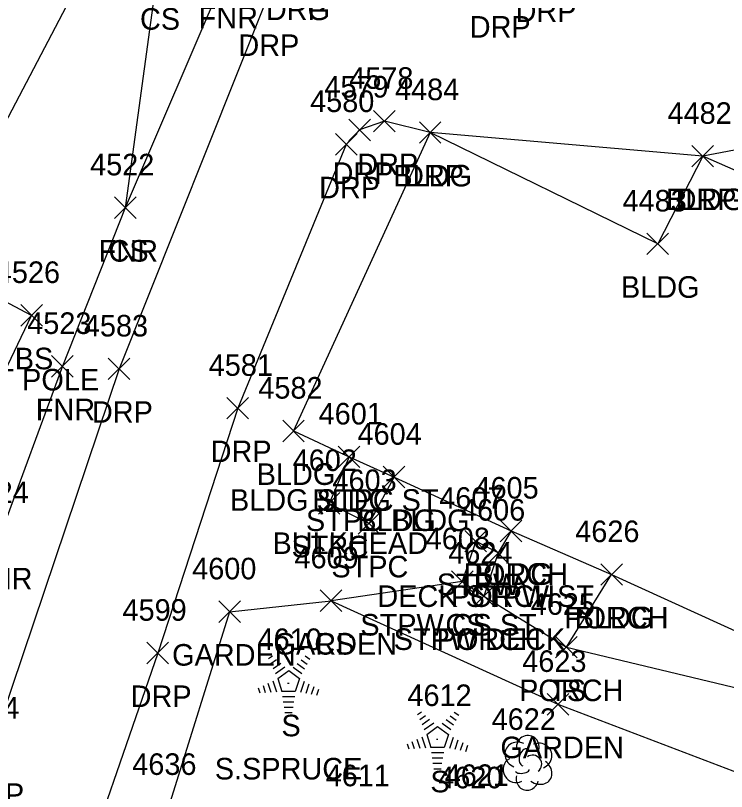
# Model space of a CAD drawing. Extents: x 49137 to 50946, y 9590 to 10709.
# Drawn here: x 50138.1 to 50204, y 10251.3 to 10323.2 of the extents above; entities that cross this region are included whole.
import ezdxf

# ---------------------------------------------------------------- set-up
doc = ezdxf.new("R2010")
doc.units = 0
for name, color, linetype in [('DCP', 7, 'Continuous'), ('L_A', 7, 'Continuous'), ('L_C', 7, 'Continuous'), ('L_I', 7, 'Continuous'), ('L_TIC', 7, 'Continuous'), ('LAPB', 7, 'Continuous'), ('LBC', 7, 'Continuous'), ('LBF', 7, 'Continuous'), ('LELB', 7, 'Continuous'), ('LFNC', 7, 'Continuous'), ('LSH', 7, 'Continuous'), ('LTC', 7, 'Continuous'), ('R_A', 7, 'Continuous'), ('R_I', 7, 'Continuous'), ('R_TIC', 7, 'Continuous'), ('RDP', 7, 'Continuous')]:
    doc.layers.add(name, color=color, linetype=linetype)

msp = doc.modelspace()

# ---------------------------------------------------------------- linework, layer by layer
at = {"layer": 'DCP'}
msp.add_lwpolyline([(49941.688, 9827.483), (50059.335, 9808.365), (50181.403, 9733.094), (50281.739, 9743.292), (50422.723, 9892.522), (50122.338, 10663.607), (50179.929, 10552.611), (50179.639, 10394.452), (50122.343, 10285.066), (50121.564, 10284.355)], dxfattribs=at)
at = {"layer": 'L_TIC'}
for points in [[(50175.537, 10311.397), (50177.537, 10313.397)], [(50177.537, 10311.397), (50175.537, 10313.397)], [(50200.782, 10309.202), (50202.782, 10311.202)], [(50202.782, 10309.202), (50200.782, 10311.202)], [(50147.29, 10304.426), (50149.29, 10306.426)], [(50149.29, 10304.426), (50147.29, 10306.426)], [(50147.29, 10304.426), (50149.29, 10306.426)], [(50149.29, 10304.426), (50147.29, 10306.426)], [(50196.617, 10301.077), (50198.617, 10303.077)], [(50198.617, 10301.077), (50196.617, 10303.077)], [(50138.611, 10294.447), (50140.611, 10296.447)], [(50140.611, 10294.447), (50138.611, 10296.447)], [(50141.462, 10289.723), (50143.462, 10291.723)], [(50143.462, 10289.723), (50141.462, 10291.723)], [(50162.875, 10283.729), (50164.875, 10285.729)], [(50164.875, 10283.729), (50162.875, 10285.729)], [(50168.018, 10281.332), (50170.018, 10283.332)], [(50170.018, 10281.332), (50168.018, 10283.332)], [(50168.018, 10281.332), (50170.018, 10283.332)], [(50170.018, 10281.332), (50168.018, 10283.332)], [(50172.191, 10279.454), (50174.191, 10281.454)], [(50174.191, 10279.454), (50172.191, 10281.454)], [(50172.191, 10279.454), (50174.191, 10281.454)], [(50174.191, 10279.454), (50172.191, 10281.454)], [(50166.179, 10277.016), (50168.179, 10279.016)], [(50168.179, 10277.016), (50166.179, 10279.016)], [(50169.868, 10275.156), (50171.868, 10277.156)], [(50171.868, 10275.156), (50169.868, 10277.156)], [(50183.024, 10274.463), (50185.024, 10276.463)], [(50185.024, 10274.463), (50183.024, 10276.463)], [(50183.024, 10274.463), (50185.024, 10276.463)], [(50185.024, 10274.463), (50183.024, 10276.463)], [(50179.759, 10273.516), (50181.759, 10275.516)], [(50181.759, 10273.516), (50179.759, 10275.516)], [(50181.832, 10272.418), (50183.832, 10274.418)], [(50183.832, 10272.418), (50181.832, 10274.418)], [(50181.832, 10272.418), (50183.832, 10274.418)], [(50183.832, 10272.418), (50181.832, 10274.418)], [(50192.337, 10270.426), (50194.337, 10272.426)], [(50194.337, 10270.426), (50192.337, 10272.426)], [(50192.337, 10270.426), (50194.337, 10272.426)], [(50194.337, 10270.426), (50192.337, 10272.426)], [(50178.503, 10269.762), (50180.503, 10271.762)], [(50180.503, 10269.762), (50178.503, 10271.762)], [(50178.503, 10269.762), (50180.503, 10271.762)], [(50180.503, 10269.762), (50178.503, 10271.762)], [(50180.515, 10268.428), (50182.515, 10270.428)], [(50182.515, 10268.428), (50180.515, 10270.428)], [(50180.515, 10268.428), (50182.515, 10270.428)], [(50182.515, 10268.428), (50180.515, 10270.428)], [(50166.358, 10267.997), (50168.358, 10269.997)], [(50168.358, 10267.997), (50166.358, 10269.997)], [(50166.358, 10267.997), (50168.358, 10269.997)], [(50168.358, 10267.997), (50166.358, 10269.997)], [(50156.957, 10266.974), (50158.957, 10268.974)], [(50158.957, 10266.974), (50156.957, 10268.974)], [(50156.957, 10266.974), (50158.957, 10268.974)], [(50158.957, 10266.974), (50156.957, 10268.974)], [(50188.154, 10263.685), (50190.154, 10265.685)], [(50190.154, 10263.685), (50188.154, 10265.685)], [(50188.154, 10263.685), (50190.154, 10265.685)], [(50190.154, 10263.685), (50188.154, 10265.685)], [(50187.374, 10258.393), (50189.374, 10260.393)], [(50189.374, 10258.393), (50187.374, 10260.393)]]:
    msp.add_lwpolyline(points, dxfattribs=at)
at = {"layer": 'LAPB'}
for points in [[(50157.957, 10267.974), (50167.358, 10268.997), (50188.374, 10259.393), (50208.468, 10251.736), (50219.606, 10243.739), (50234.01, 10243.397)], [(50157.957, 10267.974), (50152.298, 10249.844), (50148.961, 10238.473), (50151.493, 10231.517), (50159.69, 10232.278), (50178.062, 10237.469), (50196.388, 10240.519), (50210.248, 10237.84), (50211.966, 10235.094)]]:
    msp.add_lwpolyline(points, dxfattribs=at)
at = {"layer": 'LBC'}
msp.add_lwpolyline([(50270.098, 10299.898), (50238.599, 10314.069), (50235.574, 10307.905), (50226.455, 10311.856), (50221.64, 10301.448), (50201.782, 10310.202), (50197.617, 10302.077), (50176.537, 10312.397), (50163.875, 10284.729), (50169.018, 10282.332), (50173.191, 10280.454), (50184.024, 10275.463), (50193.337, 10271.426), (50216.66, 10260.799), (50221.314, 10269.876), (50239.854, 10260.408), (50236.905, 10251.43), (50234.01, 10243.397), (50235.004, 10242.826), (50235.24, 10242.798), (50259.886, 10234.748)], dxfattribs=at)
at = {"layer": 'LBF'}
for points in [[(50169.018, 10282.332), (50167.179, 10278.016), (50170.868, 10276.156), (50173.191, 10280.454)], [(50184.024, 10275.463), (50182.832, 10273.418), (50181.515, 10269.428), (50189.154, 10264.685), (50193.337, 10271.426)], [(50182.832, 10273.418), (50180.759, 10274.516), (50179.503, 10270.762), (50181.515, 10269.428)]]:
    msp.add_lwpolyline(points, dxfattribs=at)
at = {"layer": 'LELB'}
for points in [[(50126.111, 10347.947), (50139.577, 10341.078), (50151.209, 10326.927), (50148.29, 10305.426)], [(50130.767, 10276.969), (50139.611, 10295.447), (50120.307, 10305.659), (50111.788, 10297.567), (50099.22, 10268.783), (50096.624, 10253.848), (50101.814, 10247.946), (50120.352, 10244.727), (50128.611, 10261.23)], [(50179.503, 10270.762), (50167.358, 10268.997)], [(50189.154, 10264.685), (50215.463, 10258.385), (50236.905, 10251.43)]]:
    msp.add_lwpolyline(points, dxfattribs=at)
at = {"layer": 'LFNC'}
msp.add_lwpolyline([(50172.869, 10364.418), (50157.552, 10327.058), (50148.29, 10305.426), (50142.462, 10290.723), (50136.657, 10275.04), (50130.797, 10260.419), (50125.3, 10245.177), (50122.78, 10239.769), (50125.058, 10237.744)], dxfattribs=at)
at = {"layer": 'LSH'}
msp.add_line((50185.537, 10254.016), (50185.537, 10254.016), dxfattribs=at)
msp.add_line((50185.537, 10254.016), (50185.537, 10254.016), dxfattribs=at)
msp.add_arc((50185.583, 10255.45), 1.047, 335.52715, 180.95627, dxfattribs=at)
for centre, major_axis, ratio, start_param, end_param in [((50184.745, 10254.683), (1.21, -0.512), 0.895232, 1.570796, 4.712389), ((50186.578, 10254.6), (-1.141, -0.483), 0.949671, 1.570796, 4.712389), ((50185.328, 10254.475), (-0.208, -0.792), 0.645439, 3.141593, 6.283185), ((50184.453, 10253.308), (0.584, -1.042), 0.959034, 3.141593, 6.283185), ((50186.037, 10253.85), (-0.5, 0.667), 0.989748, 3.141593, 6.283185), ((50186.537, 10253.183), (-1.09, 0.792), 0.841452, 1.570796, 4.712389), ((50185.078, 10253.266), (-0.625, -0.083), 0.423636, 0, 3.141593), ((50185.537, 10252.516), (0.265, 1.061), 0.942809, 1.570796, 4.712389)]:
    msp.add_ellipse(centre, major_axis=major_axis, ratio=ratio, start_param=start_param, end_param=end_param, dxfattribs=at)
at = {"layer": 'LTC'}
for p, q in [((50161.563, 10263.63), (50161.918, 10263.888)), ((50164.962, 10263.871), (50165.381, 10263.566)), ((50161.773, 10263.165), (50162.302, 10263.549)), ((50161.983, 10262.699), (50162.686, 10263.21)), ((50164.22, 10263.174), (50164.899, 10262.68)), ((50164.591, 10263.522), (50165.14, 10263.123)), ((50162.192, 10262.233), (50163.071, 10262.871)), ((50162.417, 10261.778), (50163.428, 10262.513)), ((50163.428, 10262.513), (50164.426, 10261.788)), ((50163.848, 10262.826), (50164.658, 10262.237)), ((50161.962, 10261.559), (50162.293, 10260.54)), ((50162.417, 10261.778), (50162.804, 10260.585)), ((50164.426, 10261.788), (50164.034, 10260.585)), ((50164.863, 10261.517), (50164.525, 10260.477)), ((50160.596, 10260.91), (50160.748, 10260.442)), ((50161.051, 10261.126), (50161.263, 10260.475)), ((50161.507, 10261.343), (50161.778, 10260.507)), ((50165.308, 10261.267), (50165.02, 10260.382)), ((50165.752, 10261.017), (50165.515, 10260.287)), ((50164.034, 10260.585), (50162.804, 10260.585)), ((50163.996, 10260.085), (50162.851, 10260.085)), ((50166.196, 10260.766), (50166.01, 10260.192)), ((50163.912, 10259.585), (50162.924, 10259.585)), ((50163.828, 10259.085), (50162.997, 10259.085)), ((50175.362, 10258.437), (50175.717, 10258.694)), ((50178.761, 10258.677), (50179.18, 10258.373)), ((50163.745, 10258.585), (50163.07, 10258.585)), ((50175.572, 10257.971), (50176.101, 10258.356)), ((50175.781, 10257.506), (50176.485, 10258.017)), ((50178.018, 10257.981), (50178.698, 10257.487)), ((50178.389, 10258.329), (50178.939, 10257.93)), ((50175.991, 10257.04), (50176.869, 10257.678)), ((50176.216, 10256.585), (50177.227, 10257.319)), ((50177.227, 10257.319), (50178.224, 10256.594)), ((50177.647, 10257.632), (50178.457, 10257.044)), ((50176.216, 10256.585), (50176.603, 10255.391)), ((50178.224, 10256.594), (50177.833, 10255.391)), ((50174.85, 10255.933), (50175.062, 10255.281)), ((50175.306, 10256.149), (50175.577, 10255.314)), ((50175.761, 10256.366), (50176.092, 10255.346)), ((50178.662, 10256.324), (50178.324, 10255.284)), ((50179.106, 10256.073), (50178.819, 10255.189)), ((50179.551, 10255.823), (50179.314, 10255.094)), ((50174.395, 10255.716), (50174.547, 10255.248)), ((50177.833, 10255.391), (50176.603, 10255.391)), ((50179.995, 10255.573), (50179.808, 10254.999)), ((50177.795, 10254.891), (50176.65, 10254.891)), ((50177.711, 10254.391), (50176.723, 10254.391)), ((50177.627, 10253.891), (50176.796, 10253.891)), ((50177.543, 10253.391), (50176.868, 10253.391))]:
    msp.add_line(p, q, dxfattribs=at)
at = {"layer": 'R_TIC'}
for points in [[(50171.294, 10312.449), (50173.294, 10314.449)], [(50173.294, 10312.449), (50171.294, 10314.449)], [(50169.001, 10311.64), (50171.001, 10313.64)], [(50171.001, 10311.64), (50169.001, 10313.64)], [(50175.537, 10311.397), (50177.537, 10313.397)], [(50177.537, 10311.397), (50175.537, 10313.397)], [(50167.757, 10310.296), (50169.757, 10312.296)], [(50169.757, 10310.296), (50167.757, 10312.296)], [(50200.782, 10309.202), (50202.782, 10311.202)], [(50202.782, 10309.202), (50200.782, 10311.202)], [(50146.709, 10289.491), (50148.709, 10291.491)], [(50148.709, 10289.491), (50146.709, 10291.491)], [(50157.709, 10285.841), (50159.709, 10287.841)], [(50159.709, 10285.841), (50157.709, 10287.841)], [(50150.299, 10263.137), (50152.299, 10265.137)], [(50152.299, 10263.137), (50150.299, 10265.137)]]:
    msp.add_lwpolyline(points, dxfattribs=at)
at = {"layer": 'RDP'}
for points in [[(50268.763, 10334.964), (50257.862, 10332.021), (50248.539, 10331.099), (50231.456, 10336.06), (50208.078, 10342.301), (50200.194, 10343.46), (50196.623, 10336.903), (50193.275, 10331.325), (50186.954, 10327.655), (50182.712, 10326.192), (50176.479, 10328.282), (50171.213, 10329.686), (50166.18, 10329.046), (50163.825, 10327.815), (50161.281, 10324.491), (50147.709, 10290.491), (50135.785, 10255.064), (50128.95, 10234.24), (50121.426, 10210.517), (50116.368, 10201.092), (50105.589, 10180.051)], [(50226.455, 10311.856), (50212.894, 10312.301), (50201.782, 10310.202), (50176.537, 10312.397), (50172.294, 10313.449), (50170.001, 10312.64), (50168.757, 10311.296), (50158.709, 10286.841), (50151.299, 10264.137), (50142.801, 10239.534), (50142.923, 10234.153), (50145.299, 10229.21), (50150.303, 10224.702), (50136.97, 10219.749), (50131.758, 10217.663), (50126.002, 10213.971)]]:
    msp.add_lwpolyline(points, dxfattribs=at)

# ---------------------------------------------------------------- texts
at = {"layer": 'L_A'}
for s, p in [('CS', (50149.65, 10321.927)), ('FNR', (50155.087, 10322.058)), ('BLDG', (50173.128, 10307.397)), ('BLDG', (50198.373, 10305.202)), ('FNR', (50145.825, 10300.426)), ('CS', (50146.731, 10300.426)), ('BLDG', (50194.207, 10297.077)), ('BS', (50138.052, 10290.447)), ('FNR', (50139.997, 10285.723)), ('BLDG', (50160.465, 10279.729)), ('BLDG STPC ST', (50157.987, 10277.332)), ('BLDG', (50165.609, 10277.332)), ('STPC BLDG', (50165.026, 10275.454)), ('BLDG', (50169.782, 10275.454)), ('STPC', (50163.691, 10273.016)), ('STPC', (50167.38, 10271.156)), ('PORCH', (50179.646, 10270.463)), ('BLDG', (50180.614, 10270.463)), ('FNR', (50134.192, 10270.04)), ('STPW', (50177.153, 10269.516)), ('DECK STPW ST', (50171.644, 10268.418)), ('PORCH', (50178.455, 10268.418)), ('PORCH', (50188.959, 10266.426)), ('BLDG', (50189.928, 10266.426)), ('STPW CS ST', (50170.063, 10265.762)), ('CS', (50177.944, 10265.762)), ('GARDEN', (50162.027, 10263.997)), ('CS', (50165.799, 10263.997)), ('STPW DECK', (50173.153, 10264.428)), ('PORCH', (50177.137, 10264.428)), ('GARDEN', (50152.627, 10262.974)), ('GARDEN', (50152.627, 10262.974)), ('PORCH', (50184.776, 10259.685)), ('TS', (50187.564, 10259.685)), ('S', (50162.754, 10256.422)), ('GARDEN', (50183.043, 10254.393)), ('S', (50176.553, 10251.229))]:
    msp.add_text(s, height=2, dxfattribs=at).set_placement(p)
at = {"layer": 'L_C'}
for s, p in [('4XCHAIR LIFT SUPPORT POLE', (50106.482, 10288.485)), ('BULKHEAD', (50161.924, 10273.332)), ('S.SPRUCE', (50156.581, 10252.422))]:
    msp.add_text(s, height=2, dxfattribs=at).set_placement(p)
at = {"layer": 'L_I'}
for s, p in [('4484', (50173.278, 10315.397)), ('4482', (50198.523, 10313.202)), ('4522', (50145.03, 10308.426)), ('4522', (50145.03, 10308.426)), ('4483', (50194.357, 10305.077)), ('4526', (50136.296, 10298.447)), ('4523', (50139.202, 10293.723)), ('4582', (50160.615, 10287.729)), ('4601', (50166.199, 10285.332)), ('4601', (50166.199, 10285.332)), ('4604', (50169.805, 10283.454)), ('4604', (50169.805, 10283.454)), ('4602', (50163.794, 10281.016)), ('4603', (50167.482, 10279.156)), ('4605', (50180.638, 10278.463)), ('4605', (50180.638, 10278.463)), ('4524', (50133.397, 10278.04)), ('4607', (50177.374, 10277.516)), ('4606', (50179.392, 10276.418)), ('4606', (50179.392, 10276.418)), ('4626', (50189.975, 10274.426)), ('4626', (50189.975, 10274.426)), ('4608', (50176.118, 10273.762)), ('4608', (50176.118, 10273.762)), ('4609', (50163.964, 10271.997)), ('4609', (50163.964, 10271.997)), ('4624', (50178.208, 10272.428)), ('4624', (50178.208, 10272.428)), ('4600', (50154.485, 10270.974)), ('4600', (50154.485, 10270.974)), ('4625', (50185.847, 10267.685)), ('4625', (50185.847, 10267.685)), ('4610', (50160.542, 10264.422)), ('4623', (50185.067, 10262.393)), ('4612', (50174.427, 10259.229)), ('4622', (50182.23, 10257.016)), ('4636', (50148.936, 10252.844)), ('4611', (50166.85, 10251.791)), ('4620', (50177.279, 10251.602)), ('4621', (50177.875, 10251.819))]:
    msp.add_text(s, height=2, dxfattribs=at).set_placement(p)
at = {"layer": 'LTC'}
for p in [(50163.311, 10261.526), (50177.11, 10256.333)]:
    msp.add_text('.', height=1.037, rotation=270, dxfattribs=at).set_placement(p)
at = {"layer": 'R_A'}
for s, p in [('DRG', (50161.313, 10322.815)), ('DRP', (50161.313, 10322.815)), ('DRP', (50184.443, 10322.655)), ('DRP', (50180.2, 10321.192)), ('DRP', (50158.769, 10319.491)), ('DRP', (50169.782, 10308.449)), ('DRP', (50167.489, 10307.64)), ('DRP', (50174.025, 10307.397)), ('DRP', (50166.245, 10306.296)), ('DRP', (50199.271, 10305.202)), ('DRP', (50145.198, 10285.491)), ('DRP', (50156.197, 10281.841)), ('DRP', (50148.787, 10259.137)), ('DRP', (50133.273, 10250.064))]:
    msp.add_text(s, height=2, dxfattribs=at).set_placement(p)
at = {"layer": 'R_I'}
for s, p in [('4578', (50169.034, 10316.449)), ('4579', (50166.733, 10315.64)), ('4484', (50173.278, 10315.397)), ('4580', (50165.411, 10314.296)), ('4482', (50198.523, 10313.202)), ('4583', (50144.45, 10293.491)), ('4581', (50156.016, 10289.841)), ('4599', (50148.031, 10267.137)), ('4584', (50132.525, 10258.064))]:
    msp.add_text(s, height=2, dxfattribs=at).set_placement(p)

doc.saveas('drawing.dxf')
